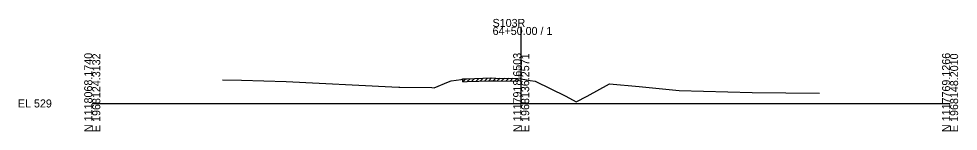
# Model space of a CAD drawing. Extents: x 974 to 1303, y 990 to 10019.
# Drawn here: x 974.3 to 1302.8, y 6990.3 to 7029.6 of the extents above; entities that cross this region are included whole.
import ezdxf

# ---------------------------------------------------------------- set-up
doc = ezdxf.new("R2010")
doc.units = 0
for name, color, linetype in [('Level 10', 7, 'Continuous'), ('Level 60', 7, 'Continuous'), ('Level 61', 7, 'Continuous'), ('Level 63', 7, 'Continuous')]:
    doc.layers.add(name, color=color, linetype=linetype)

msp = doc.modelspace()

# ---------------------------------------------------------------- linework, layer by layer
at = {"layer": 'Level 60'}
for p, q in [((1045.58, 7008.29), (1052.24, 7008.17)), ((1052.24, 7008.17), (1067.83, 7007.64)), ((1067.83, 7007.64), (1104.74, 7005.81)), ((1124.56, 7007.51), (1125.48, 7007.87)), ((1125.48, 7007.87), (1129, 7008.42)), ((1129, 7008.42), (1129.65, 7008.56)), ((1129.65, 7008.56), (1131.12, 7008.62)), ((1131.12, 7008.62), (1139.25, 7008.91)), ((1139.25, 7008.91), (1141.17, 7008.89)), ((1141.17, 7008.89), (1148.87, 7008.75)), ((1148.87, 7008.75), (1150, 7008.57)), ((1150, 7008.57), (1153.11, 7008.06)), ((1153.11, 7008.06), (1154.93, 7007.75)), ((1154.93, 7007.75), (1165.67, 7002.54)), ((1104.74, 7005.81), (1107.2, 7005.7)), ((1107.2, 7005.7), (1107.52, 7005.69)), ((1107.52, 7005.69), (1118.72, 7005.57)), ((1118.72, 7005.57), (1119.56, 7005.47)), ((1119.56, 7005.47), (1124.56, 7007.51)), ((1173.07, 7002.57), (1180.88, 7006.8)), ((1180.88, 7006.8), (1191.3, 7005.88)), ((1191.3, 7005.88), (1205.22, 7004.51)), ((1205.22, 7004.51), (1230.83, 7003.88)), ((1165.67, 7002.54), (1169.25, 7000.6)), ((1169.25, 7000.6), (1173.07, 7002.57)), ((1230.83, 7003.88), (1254.28, 7003.64))]:
    msp.add_line(p, q, dxfattribs=at)
at = {"layer": 'Level 61'}
for p, q in [((1129.65, 7007.56), (1130.69, 7008.61)), ((1129.65, 7007.56), (1129.65, 7008.56)), ((1129.65, 7007.56), (1131.12, 7007.62)), ((1131.12, 7007.62), (1139.25, 7007.91)), ((1131.15, 7007.62), (1132.18, 7008.66)), ((1132.65, 7007.68), (1133.68, 7008.71)), ((1134.15, 7007.73), (1135.18, 7008.77)), ((1135.65, 7007.78), (1136.68, 7008.82)), ((1137.15, 7007.84), (1138.18, 7008.87)), ((1138.65, 7007.89), (1139.66, 7008.91)), ((1139.25, 7007.91), (1141.17, 7007.89)), ((1140.15, 7007.9), (1141.13, 7008.89)), ((1141.17, 7007.89), (1148.87, 7007.75)), ((1141.65, 7007.88), (1142.63, 7008.86)), ((1143.15, 7007.85), (1144.13, 7008.83)), ((1144.65, 7007.82), (1145.63, 7008.81)), ((1146.15, 7007.8), (1147.13, 7008.78)), ((1147.65, 7007.77), (1148.63, 7008.75)), ((1148.87, 7008.75), (1148.87, 7007.75)), ((1148.87, 7007.75), (1148.87, 7007.75))]:
    msp.add_line(p, q, dxfattribs=at)
at = {"layer": 'Level 63'}
for p, q in [((1150, 7000), (1150, 7026.74)), ((1000, 7000), (1150, 7000)), ((1150, 7000), (1300, 7000))]:
    msp.add_line(p, q, dxfattribs=at)

# ---------------------------------------------------------------- texts
at = {"layer": 'Level 10'}
msp.add_text('537.57', height=0.9, rotation=90, dxfattribs=at).set_placement((1149.95, 7009.07))
at = {"layer": 'Level 63'}
for s, p in [('S103R', (1140, 7026.74)), ('64+50.00 / 1', (1140, 7023.94)), ('EL 529', (974, 6998.6))]:
    msp.add_text(s, height=2.8, dxfattribs=at).set_placement(p)
for s, p in [('N 1118068.1740', (1000, 6990)), ('N 1117918.6503', (1150, 6990)), ('N 1117769.1266', (1300, 6990)), ('E 1968124.3132', (1002.8, 6990)), ('E 1968136.2571', (1152.8, 6990)), ('E 1968148.2010', (1302.8, 6990))]:
    msp.add_text(s, height=2.8, rotation=90, dxfattribs=at).set_placement(p)

doc.saveas('drawing.dxf')
